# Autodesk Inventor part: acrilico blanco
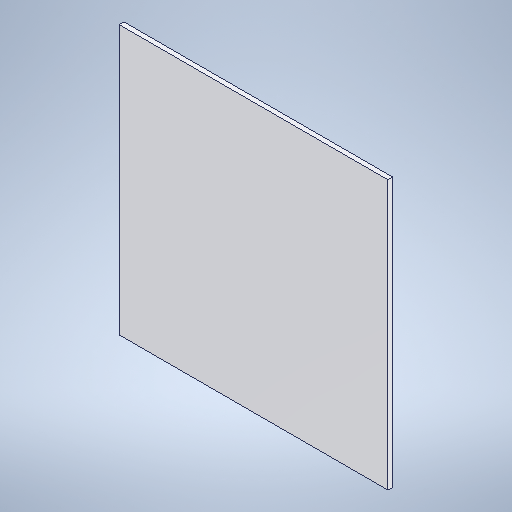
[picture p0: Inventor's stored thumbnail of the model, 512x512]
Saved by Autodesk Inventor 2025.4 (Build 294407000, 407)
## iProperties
Created: 2026-04
Part Number: acrilico blanco
Material: PBT Plastic
Document SubType Name: Modeling
Designer: I11112
Density: 1.31 g/cm^3
Appearance: PTFE
Author: I11112
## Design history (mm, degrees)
sketch "Sketch1"
  geometry: L1 (110, 110)-(-110, 110); L2 (-110, 110)-(-110, -110); L3 (-110, -110)-(110, -110); L4 (110, -110)-(110, 110); L5 (110, 110)-(-110, -110); L6 (-110, 110)-(110, -110); 1 further point
  constraints: 12 end point, 2 midpoint, 2 parallel, 1 horizontal, 1 perpendicular
  dimensions: "d0" = 220 distance of L3.end L2.end; "d1" = 220 distance of L2.end L1.end
extrude "Extrusion1" new body sketch "Sketch1" distance "d2" = 3.9; taper "d3" = 0 deg
body "Solid1"
